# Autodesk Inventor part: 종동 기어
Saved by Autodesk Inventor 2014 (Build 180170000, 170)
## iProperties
Created: 2026-04
Part Number: 종동 기어
Material: 강철, 탄소
Document SubType Name: Modeling
Designer: dg
Density: 7.87 g/cm^3
Appearance: 반연마
Author: jhkim
Creation Date: 2026-03-27
Sending System: Autodesk Inventor 2026
Preprocessor: ST-DEVELOPER v20.1
Author: dg
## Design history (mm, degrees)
node "종동 기어1"
node "솔리드1"
node "기준1"
